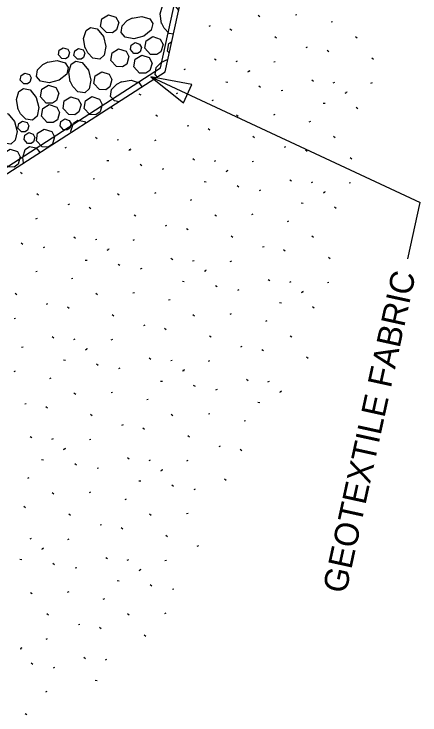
# Model space of a CAD drawing. Extents: x 2126110 to 2128246, y 1804858 to 1811658.
# Drawn here: x 2126790.5 to 2126875.2, y 1806272.7 to 1806418.7 of the extents above; entities that cross this region are included whole.
import ezdxf

# ---------------------------------------------------------------- set-up
doc = ezdxf.new("R2010")
doc.units = 0
doc.layers.add('1', color=7, linetype='Continuous')

msp = doc.modelspace()

# ---------------------------------------------------------------- linework, layer by layer
at = {"layer": '1'}
for p, q in [((2126821.03, 1806407.52), (2126844.25, 1806513.73)), ((2126822.04, 1806406.65), (2126845.41, 1806513.57)), ((2126849.19, 1806418.53), (2126849.48, 1806418.64)), ((2126841.78, 1806418.14), (2126841.43, 1806418.4)), ((2126856.62, 1806417.07), (2126856.92, 1806417.19)), ((2126831.16, 1806416.18), (2126831.46, 1806416.3)), ((2126835.89, 1806415.3), (2126835.53, 1806415.55)), ((2126845.22, 1806413.71), (2126844.87, 1806413.97)), ((2126862.04, 1806413.72), (2126861.69, 1806413.97)), ((2126851.42, 1806411.75), (2126851.72, 1806411.87)), ((2126856.15, 1806410.87), (2126855.8, 1806411.13)), ((2126822.22, 1806409.16), (2126822.61, 1806409.23)), ((2126832.67, 1806409.09), (2126832.31, 1806409.35)), ((2126836.82, 1806408.84), (2126837.12, 1806408.96)), ((2126844.67, 1806408.74), (2126844.97, 1806408.86)), ((2126865.49, 1806409.28), (2126865.13, 1806409.54)), ((2126742.89, 1806357.1), (2126821.03, 1806407.52)), ((2126825.97, 1806407.2), (2126826.27, 1806407.31)), ((2126839.41, 1806406.84), (2126839.71, 1806406.96)), ((2126743.85, 1806356.5), (2126822.04, 1806406.65)), ((2126819, 1806405.64), (2126875.16, 1806379.47)), ((2126839.28, 1806406.69), (2126839.58, 1806406.81)), ((2126834.69, 1806404.59), (2126835.09, 1806404.55)), ((2126852.93, 1806404.66), (2126852.58, 1806404.92)), ((2126857.08, 1806404.42), (2126857.38, 1806404.53)), ((2126864.93, 1806404.32), (2126865.23, 1806404.43)), ((2126841.93, 1806403.43), (2126841.58, 1806403.69)), ((2126846.23, 1806402.77), (2126846.53, 1806402.89)), ((2126859.68, 1806402.42), (2126859.97, 1806402.53)), ((2126816.98, 1806401.79), (2126816.62, 1806402.05)), ((2126824.38, 1806402.17), (2126824.68, 1806402.29)), ((2126859.54, 1806402.26), (2126859.84, 1806402.38)), ((2126831.82, 1806400.72), (2126832.12, 1806400.84)), ((2126854.95, 1806400.16), (2126855.35, 1806400.12)), ((2126811.08, 1806398.95), (2126810.73, 1806399.2)), ((2126862.2, 1806399), (2126861.84, 1806399.26)), ((2126820.42, 1806397.36), (2126820.07, 1806397.62)), ((2126837.24, 1806397.37), (2126836.89, 1806397.62)), ((2126844.65, 1806397.75), (2126844.94, 1806397.86)), ((2126826.62, 1806395.4), (2126826.92, 1806395.52)), ((2126852.08, 1806396.29), (2126852.38, 1806396.41)), ((2126831.34, 1806394.52), (2126830.99, 1806394.78)), ((2126807.86, 1806392.74), (2126807.51, 1806393)), ((2126812.02, 1806392.49), (2126812.32, 1806392.61)), ((2126819.87, 1806392.39), (2126820.17, 1806392.51)), ((2126840.68, 1806392.93), (2126840.33, 1806393.19)), ((2126857.5, 1806392.94), (2126857.15, 1806393.2)), ((2126801.17, 1806390.85), (2126801.47, 1806390.96)), ((2126846.88, 1806390.97), (2126847.18, 1806391.09)), ((2126814.47, 1806390.34), (2126814.77, 1806390.46)), ((2126814.61, 1806390.49), (2126814.91, 1806390.61)), ((2126851.61, 1806390.09), (2126851.25, 1806390.35)), ((2126809.88, 1806388.24), (2126810.28, 1806388.2)), ((2126828.13, 1806388.31), (2126827.77, 1806388.57)), ((2126832.28, 1806388.07), (2126832.58, 1806388.18)), ((2126840.13, 1806387.97), (2126840.43, 1806388.08)), ((2126860.95, 1806388.5), (2126860.59, 1806388.76)), ((2126817.13, 1806387.08), (2126816.78, 1806387.34)), ((2126821.43, 1806386.42), (2126821.73, 1806386.54)), ((2126792.17, 1806385.44), (2126791.82, 1806385.7)), ((2126799.58, 1806385.82), (2126799.88, 1806385.94)), ((2126834.74, 1806385.91), (2126835.03, 1806386.03)), ((2126834.87, 1806386.07), (2126835.17, 1806386.18)), ((2126807.02, 1806384.37), (2126807.31, 1806384.49)), ((2126830.15, 1806383.81), (2126830.55, 1806383.77)), ((2126848.39, 1806383.89), (2126848.04, 1806384.14)), ((2126852.54, 1806383.64), (2126852.84, 1806383.76)), ((2126860.39, 1806383.54), (2126860.69, 1806383.65)), ((2126837.39, 1806382.65), (2126837.04, 1806382.91)), ((2126841.69, 1806381.99), (2126841.99, 1806382.11)), ((2126795.62, 1806381.01), (2126795.27, 1806381.27)), ((2126812.44, 1806381.01), (2126812.08, 1806381.27)), ((2126819.84, 1806381.4), (2126820.14, 1806381.51)), ((2126855, 1806381.49), (2126855.3, 1806381.6)), ((2126855.14, 1806381.64), (2126855.43, 1806381.75)), ((2126801.82, 1806379.05), (2126802.12, 1806379.17)), ((2126827.28, 1806379.94), (2126827.58, 1806380.06)), ((2126850.41, 1806379.39), (2126850.81, 1806379.34)), ((2126872.59, 1806367.74), (2126875.16, 1806379.47)), ((2126806.54, 1806378.17), (2126806.19, 1806378.43)), ((2126857.66, 1806378.22), (2126857.3, 1806378.48)), ((2126815.88, 1806376.58), (2126815.53, 1806376.84)), ((2126832.7, 1806376.59), (2126832.35, 1806376.85)), ((2126840.1, 1806376.97), (2126840.4, 1806377.08)), ((2126795.06, 1806376.04), (2126795.36, 1806376.16)), ((2126822.08, 1806374.62), (2126822.38, 1806374.74)), ((2126847.54, 1806375.51), (2126847.84, 1806375.63)), ((2126826.8, 1806373.74), (2126826.45, 1806374)), ((2126803.32, 1806371.96), (2126802.97, 1806372.22)), ((2126807.48, 1806371.72), (2126807.78, 1806371.83)), ((2126836.14, 1806372.15), (2126835.79, 1806372.41)), ((2126852.96, 1806372.16), (2126852.61, 1806372.42)), ((2126792.33, 1806370.73), (2126791.97, 1806370.99)), ((2126815.33, 1806371.61), (2126815.63, 1806371.73)), ((2126796.63, 1806370.07), (2126796.93, 1806370.19)), ((2126809.93, 1806369.56), (2126810.23, 1806369.68)), ((2126810.07, 1806369.71), (2126810.37, 1806369.83)), ((2126842.34, 1806370.19), (2126842.64, 1806370.31)), ((2126847.07, 1806369.31), (2126846.71, 1806369.57)), ((2126805.34, 1806367.46), (2126805.74, 1806367.42)), ((2126823.59, 1806367.53), (2126823.23, 1806367.79)), ((2126856.41, 1806367.72), (2126856.05, 1806367.98)), ((2126812.59, 1806366.3), (2126812.24, 1806366.56)), ((2126827.74, 1806367.29), (2126828.04, 1806367.4)), ((2126835.59, 1806367.19), (2126835.89, 1806367.3)), ((2126795.04, 1806365.05), (2126795.34, 1806365.16)), ((2126816.89, 1806365.64), (2126817.19, 1806365.76)), ((2126830.2, 1806365.13), (2126830.49, 1806365.25)), ((2126830.33, 1806365.29), (2126830.63, 1806365.4)), ((2126802.48, 1806363.59), (2126802.77, 1806363.71)), ((2126843.85, 1806363.11), (2126843.5, 1806363.37)), ((2126825.61, 1806363.04), (2126826.01, 1806362.99)), ((2126832.85, 1806361.87), (2126832.5, 1806362.13)), ((2126848, 1806362.86), (2126848.3, 1806362.98)), ((2126855.85, 1806362.76), (2126856.15, 1806362.88)), ((2126791.08, 1806360.23), (2126790.73, 1806360.49)), ((2126807.9, 1806360.24), (2126807.54, 1806360.5)), ((2126815.3, 1806360.62), (2126815.6, 1806360.73)), ((2126837.15, 1806361.21), (2126837.45, 1806361.33)), ((2126850.46, 1806360.71), (2126850.76, 1806360.82)), ((2126850.6, 1806360.86), (2126850.89, 1806360.98)), ((2126822.74, 1806359.16), (2126823.04, 1806359.28)), ((2126797.28, 1806358.27), (2126797.58, 1806358.39)), ((2126802, 1806357.39), (2126801.65, 1806357.65)), ((2126845.87, 1806358.61), (2126846.27, 1806358.57)), ((2126853.11, 1806357.44), (2126852.76, 1806357.7)), ((2126811.34, 1806355.8), (2126810.99, 1806356.06)), ((2126828.16, 1806355.81), (2126827.81, 1806356.07)), ((2126835.56, 1806356.19), (2126835.86, 1806356.31)), ((2126790.52, 1806355.26), (2126790.82, 1806355.38)), ((2126843, 1806354.74), (2126843.3, 1806354.85)), ((2126817.54, 1806353.84), (2126817.84, 1806353.96)), ((2126822.26, 1806352.96), (2126821.91, 1806353.22)), ((2126798.78, 1806351.18), (2126798.43, 1806351.44)), ((2126831.6, 1806351.37), (2126831.25, 1806351.63)), ((2126848.42, 1806351.38), (2126848.07, 1806351.64)), ((2126802.94, 1806350.94), (2126803.24, 1806351.05)), ((2126810.79, 1806350.84), (2126811.09, 1806350.95)), ((2126792.09, 1806349.29), (2126792.39, 1806349.41)), ((2126805.39, 1806348.78), (2126805.69, 1806348.9)), ((2126805.53, 1806348.94), (2126805.83, 1806349.05)), ((2126837.8, 1806349.42), (2126838.1, 1806349.53)), ((2126842.53, 1806348.53), (2126842.17, 1806348.79)), ((2126819.04, 1806346.76), (2126818.69, 1806347.01)), ((2126851.87, 1806346.95), (2126851.51, 1806347.21)), ((2126800.8, 1806346.68), (2126801.2, 1806346.64)), ((2126808.05, 1806345.52), (2126807.7, 1806345.78)), ((2126823.2, 1806346.51), (2126823.5, 1806346.63)), ((2126831.05, 1806346.41), (2126831.35, 1806346.52)), ((2126790.5, 1806344.27), (2126790.8, 1806344.38)), ((2126812.35, 1806344.86), (2126812.65, 1806344.98)), ((2126825.66, 1806344.36), (2126825.95, 1806344.47)), ((2126825.79, 1806344.51), (2126826.09, 1806344.63)), ((2126797.94, 1806342.81), (2126798.23, 1806342.93)), ((2126821.07, 1806342.26), (2126821.47, 1806342.22)), ((2126828.31, 1806341.09), (2126827.96, 1806341.35)), ((2126839.31, 1806342.33), (2126838.95, 1806342.59)), ((2126843.46, 1806342.08), (2126843.76, 1806342.2)), ((2126803.36, 1806339.46), (2126803, 1806339.72)), ((2126810.76, 1806339.84), (2126811.06, 1806339.96)), ((2126832.61, 1806340.44), (2126832.91, 1806340.55)), ((2126845.92, 1806339.93), (2126846.22, 1806340.05)), ((2126846.06, 1806340.08), (2126846.35, 1806340.2)), ((2126818.2, 1806338.38), (2126818.5, 1806338.5)), ((2126792.74, 1806337.49), (2126793.04, 1806337.61)), ((2126797.46, 1806336.61), (2126797.11, 1806336.87)), ((2126841.33, 1806337.83), (2126841.73, 1806337.79)), ((2126823.62, 1806335.03), (2126823.27, 1806335.29)), ((2126831.02, 1806335.41), (2126831.32, 1806335.53)), ((2126806.8, 1806335.02), (2126806.45, 1806335.28)), ((2126838.46, 1806333.96), (2126838.76, 1806334.07)), ((2126813, 1806333.06), (2126813.3, 1806333.18)), ((2126817.72, 1806332.18), (2126817.37, 1806332.44)), ((2126794.24, 1806330.41), (2126793.89, 1806330.66)), ((2126798.4, 1806330.16), (2126798.7, 1806330.28)), ((2126806.25, 1806330.06), (2126806.54, 1806330.17)), ((2126827.06, 1806330.6), (2126826.71, 1806330.85)), ((2126800.85, 1806328.01), (2126801.15, 1806328.12)), ((2126800.99, 1806328.16), (2126801.29, 1806328.27)), ((2126833.26, 1806328.64), (2126833.56, 1806328.75)), ((2126837.99, 1806327.75), (2126837.63, 1806328.01)), ((2126796.26, 1806325.91), (2126796.66, 1806325.86)), ((2126814.5, 1806325.98), (2126814.15, 1806326.24)), ((2126818.66, 1806325.73), (2126818.96, 1806325.85)), ((2126826.51, 1806325.63), (2126826.81, 1806325.75)), ((2126803.51, 1806324.74), (2126803.16, 1806325)), ((2126807.81, 1806324.08), (2126808.11, 1806324.2)), ((2126821.12, 1806323.58), (2126821.41, 1806323.69)), ((2126821.25, 1806323.73), (2126821.55, 1806323.85)), ((2126793.39, 1806322.03), (2126793.69, 1806322.15)), ((2126816.53, 1806321.48), (2126816.93, 1806321.44)), ((2126834.77, 1806321.55), (2126834.41, 1806321.81)), ((2126823.77, 1806320.32), (2126823.42, 1806320.57)), ((2126828.07, 1806319.66), (2126828.37, 1806319.77)), ((2126798.81, 1806318.68), (2126798.46, 1806318.94)), ((2126806.22, 1806319.06), (2126806.52, 1806319.18)), ((2126813.66, 1806317.61), (2126813.96, 1806317.72)), ((2126792.92, 1806315.83), (2126792.57, 1806316.09)), ((2126802.26, 1806314.25), (2126801.91, 1806314.5)), ((2126819.08, 1806314.25), (2126818.72, 1806314.51)), ((2126826.48, 1806314.63), (2126826.78, 1806314.75)), ((2126808.46, 1806312.29), (2126808.76, 1806312.4)), ((2126813.18, 1806311.4), (2126812.83, 1806311.66)), ((2126793.86, 1806309.38), (2126794.16, 1806309.5)), ((2126801.71, 1806309.28), (2126802, 1806309.4)), ((2126822.52, 1806309.82), (2126822.17, 1806310.08)), ((2126828.72, 1806307.86), (2126829.02, 1806307.98)), ((2126796.31, 1806307.23), (2126796.61, 1806307.34)), ((2126796.45, 1806307.38), (2126796.75, 1806307.5)), ((2126791.72, 1806305.13), (2126792.12, 1806305.09)), ((2126809.96, 1806305.2), (2126809.61, 1806305.46)), ((2126814.12, 1806304.95), (2126814.42, 1806305.07)), ((2126821.97, 1806304.85), (2126822.27, 1806304.97)), ((2126798.97, 1806303.97), (2126798.62, 1806304.22)), ((2126803.27, 1806303.31), (2126803.57, 1806303.42)), ((2126816.57, 1806302.8), (2126816.87, 1806302.92)), ((2126816.71, 1806302.95), (2126817.01, 1806303.07)), ((2126811.99, 1806300.7), (2126812.39, 1806300.66)), ((2126819.23, 1806299.54), (2126818.88, 1806299.8)), ((2126823.53, 1806298.88), (2126823.83, 1806299)), ((2126794.27, 1806297.9), (2126793.92, 1806298.16)), ((2126801.68, 1806298.28), (2126801.98, 1806298.4)), ((2126809.12, 1806296.83), (2126809.42, 1806296.94)), ((2126797.72, 1806293.47), (2126797.37, 1806293.73)), ((2126814.54, 1806293.47), (2126814.18, 1806293.73)), ((2126821.94, 1806293.85), (2126822.24, 1806293.97)), ((2126803.92, 1806291.51), (2126804.22, 1806291.62)), ((2126808.64, 1806290.63), (2126808.29, 1806290.88)), ((2126797.17, 1806288.5), (2126797.46, 1806288.62)), ((2126817.98, 1806289.04), (2126817.63, 1806289.3)), ((2126791.77, 1806286.45), (2126792.07, 1806286.57)), ((2126791.91, 1806286.6), (2126792.21, 1806286.72)), ((2126805.42, 1806284.42), (2126805.07, 1806284.68)), ((2126809.58, 1806284.17), (2126809.88, 1806284.29)), ((2126794.43, 1806283.19), (2126794.08, 1806283.45)), ((2126798.73, 1806282.53), (2126799.03, 1806282.64)), ((2126807.45, 1806279.92), (2126807.84, 1806279.88)), ((2126797.14, 1806277.5), (2126797.44, 1806277.62)), ((2126793.18, 1806272.69), (2126792.83, 1806272.95))]:
    msp.add_line(p, q, dxfattribs=at)
for points in [[(2126821.27, 1806416.78), (2126820.94, 1806418.78), (2126821.46, 1806420.44), (2126822.4, 1806421.08), (2126823.77, 1806420.75), (2126824.84, 1806419.45)], [(2126809.75, 1806414.85), (2126808.56, 1806416.14), (2126808.81, 1806417.74), (2126810.19, 1806418.58), (2126811.74, 1806418.08), (2126812.34, 1806416.93), (2126811.88, 1806415.4), (2126811.02, 1806414.82), (2126809.75, 1806414.85)], [(2126815.13, 1806417.89), (2126817.13, 1806418.22), (2126818.79, 1806417.7), (2126819.43, 1806416.76), (2126819.11, 1806415.39), (2126817.54, 1806414.1), (2126815.45, 1806413.57), (2126813.67, 1806413.93), (2126812.82, 1806414.86), (2126813.03, 1806416.29), (2126814.12, 1806417.38), (2126815.22, 1806417.92)], [(2126805.35, 1806411.64), (2126805.02, 1806413.64), (2126805.54, 1806415.3), (2126806.48, 1806415.94), (2126807.84, 1806415.62), (2126809.14, 1806414.05), (2126809.67, 1806411.96), (2126809.31, 1806410.17), (2126808.38, 1806409.33), (2126806.95, 1806409.54), (2126805.86, 1806410.63), (2126805.32, 1806411.73)], [(2126823.77, 1806414.55), (2126822.87, 1806414.68), (2126821.78, 1806415.77), (2126821.24, 1806416.86)], [(2126815.49, 1806410.52), (2126814.78, 1806411.3), (2126814.93, 1806412.25), (2126815.76, 1806412.76), (2126816.69, 1806412.46), (2126817.05, 1806411.77), (2126816.78, 1806410.85), (2126816.26, 1806410.51), (2126815.49, 1806410.52)], [(2126818.99, 1806410.29), (2126817.8, 1806411.58), (2126818.06, 1806413.17), (2126819.43, 1806414.02), (2126820.98, 1806413.51), (2126821.58, 1806412.36), (2126821.13, 1806410.83), (2126820.26, 1806410.26), (2126818.99, 1806410.29)], [(2126822.9, 1806410.58), (2126822.51, 1806411.01), (2126822.76, 1806412.6), (2126823.44, 1806413.02)], [(2126800.5, 1806409.43), (2126799.79, 1806410.21), (2126799.94, 1806411.16), (2126800.76, 1806411.67), (2126801.7, 1806411.37), (2126802.05, 1806410.68), (2126801.78, 1806409.76), (2126801.26, 1806409.42), (2126800.5, 1806409.43)], [(2126803.71, 1806409.32), (2126803, 1806410.1), (2126803.15, 1806411.05), (2126803.97, 1806411.56), (2126804.91, 1806411.26), (2126805.27, 1806410.57), (2126804.99, 1806409.65), (2126804.47, 1806409.31), (2126803.71, 1806409.32)], [(2126811.88, 1806407.77), (2126810.7, 1806409.06), (2126810.95, 1806410.65), (2126812.32, 1806411.5), (2126813.88, 1806410.99), (2126814.47, 1806409.84), (2126814.02, 1806408.31), (2126813.15, 1806407.74), (2126811.88, 1806407.77)], [(2126816.69, 1806406.43), (2126815.5, 1806407.72), (2126815.76, 1806409.31), (2126817.13, 1806410.16), (2126818.68, 1806409.65), (2126819.28, 1806408.5), (2126818.83, 1806406.97), (2126817.96, 1806406.4), (2126816.69, 1806406.43)], [(2126797.51, 1806408.72), (2126799.51, 1806409.05), (2126801.18, 1806408.53), (2126801.81, 1806407.59), (2126801.49, 1806406.22), (2126799.92, 1806404.93), (2126797.83, 1806404.4), (2126796.05, 1806404.76), (2126795.2, 1806405.69), (2126795.41, 1806407.12), (2126796.5, 1806408.21), (2126797.6, 1806408.75)], [(2126802.23, 1806404.63), (2126801.9, 1806406.63), (2126802.42, 1806408.29), (2126803.36, 1806408.93), (2126804.73, 1806408.6), (2126806.02, 1806407.04), (2126806.55, 1806404.95), (2126806.2, 1806403.16), (2126805.27, 1806402.32), (2126803.83, 1806402.53), (2126802.74, 1806403.62), (2126802.2, 1806404.71)], [(2126820.39, 1806405.59), (2126819.9, 1806406.13), (2126820.12, 1806407.57), (2126821.21, 1806408.65), (2126822.3, 1806409.19)], [(2126792.52, 1806404.19), (2126791.81, 1806404.96), (2126791.96, 1806405.92), (2126792.78, 1806406.42), (2126793.72, 1806406.12), (2126794.07, 1806405.43), (2126793.8, 1806404.51), (2126793.28, 1806404.17), (2126792.52, 1806404.19)], [(2126808.34, 1806402.98), (2126807.15, 1806404.27), (2126807.41, 1806405.87), (2126808.78, 1806406.71), (2126810.33, 1806406.21), (2126810.93, 1806405.06), (2126810.48, 1806403.53), (2126809.61, 1806402.95), (2126808.34, 1806402.98)], [(2126812.39, 1806400.45), (2126811.45, 1806400.64), (2126810.6, 1806401.57), (2126810.82, 1806403.01), (2126811.91, 1806404.1), (2126813, 1806404.64)], [(2126812.91, 1806404.61), (2126814.92, 1806404.93), (2126816.58, 1806404.42), (2126817.18, 1806403.53)], [(2126791.34, 1806398.93), (2126791.01, 1806400.93), (2126791.53, 1806402.59), (2126792.47, 1806403.23), (2126793.84, 1806402.9), (2126795.13, 1806401.34), (2126795.66, 1806399.25), (2126795.31, 1806397.46), (2126794.38, 1806396.62), (2126792.94, 1806396.83), (2126791.85, 1806397.92), (2126791.31, 1806399.01)], [(2126797.22, 1806400.17), (2126796.03, 1806401.46), (2126796.28, 1806403.06), (2126797.66, 1806403.9), (2126799.21, 1806403.4), (2126799.81, 1806402.25), (2126799.36, 1806400.72), (2126798.49, 1806400.15), (2126797.22, 1806400.17)], [(2126801.91, 1806397.77), (2126800.72, 1806399.06), (2126800.97, 1806400.66), (2126802.35, 1806401.5), (2126803.9, 1806401), (2126804.5, 1806399.85), (2126804.04, 1806398.32), (2126803.18, 1806397.74), (2126801.91, 1806397.77)], [(2126806.3, 1806397.78), (2126805.12, 1806399.07), (2126805.37, 1806400.67), (2126806.74, 1806401.51), (2126808.3, 1806401.01), (2126808.89, 1806399.86), (2126808.44, 1806398.33), (2126807.57, 1806397.75), (2126806.3, 1806397.78)], [(2126797.41, 1806396.13), (2126796.22, 1806397.42), (2126796.48, 1806399.01), (2126797.85, 1806399.86), (2126799.4, 1806399.35), (2126800, 1806398.2), (2126799.55, 1806396.68), (2126798.68, 1806396.1), (2126797.41, 1806396.13)], [(2126786.8, 1806393.93), (2126786.47, 1806395.93), (2126786.99, 1806397.59), (2126787.93, 1806398.23), (2126789.3, 1806397.91), (2126790.59, 1806396.34), (2126791.12, 1806394.25), (2126790.76, 1806392.46), (2126789.83, 1806391.62), (2126788.4, 1806391.83), (2126787.31, 1806392.92), (2126786.77, 1806394.01)], [(2126800.84, 1806394.62), (2126800.13, 1806395.4), (2126800.28, 1806396.35), (2126801.1, 1806396.86), (2126802.03, 1806396.56), (2126802.39, 1806395.87), (2126802.12, 1806394.95), (2126801.6, 1806394.61), (2126800.84, 1806394.62)], [(2126802.41, 1806394.05), (2126802.36, 1806394.33), (2126802.88, 1806395.99), (2126803.82, 1806396.63), (2126805.19, 1806396.31), (2126805.44, 1806396)], [(2126792.03, 1806394.18), (2126791.31, 1806394.95), (2126791.47, 1806395.91), (2126792.29, 1806396.41), (2126793.22, 1806396.11), (2126793.58, 1806395.42), (2126793.31, 1806394.51), (2126792.79, 1806394.16), (2126792.03, 1806394.18)], [(2126793.29, 1806391.77), (2126792.58, 1806392.55), (2126792.73, 1806393.5), (2126793.56, 1806394.01), (2126794.49, 1806393.71), (2126794.85, 1806393.02), (2126794.57, 1806392.1), (2126794.05, 1806391.75), (2126793.29, 1806391.77)], [(2126796.36, 1806391.03), (2126795.17, 1806392.32), (2126795.42, 1806393.92), (2126796.8, 1806394.76), (2126798.35, 1806394.26), (2126798.95, 1806393.11), (2126798.5, 1806391.58), (2126797.63, 1806391), (2126796.36, 1806391.03)], [(2126792.49, 1806387.7), (2126792.31, 1806388.85), (2126792.82, 1806390.51), (2126793.76, 1806391.15), (2126795.13, 1806390.82), (2126795.91, 1806389.88)], [(2126789.22, 1806386.87), (2126788.04, 1806388.16), (2126788.29, 1806389.75), (2126789.67, 1806390.6), (2126791.22, 1806390.09), (2126791.81, 1806388.94), (2126791.36, 1806387.42), (2126790.5, 1806386.84), (2126789.22, 1806386.87)]]:
    msp.add_lwpolyline(points, dxfattribs=at)
msp.add_lwpolyline([(2126827.55, 1806404.07), (2126819, 1806405.64), (2126825.81, 1806400.23)], close=True, dxfattribs=at)

# ---------------------------------------------------------------- texts
msp.add_text('GEOTEXTILE FABRIC', height=5, rotation=77.6736, dxfattribs=at).set_placement((2126859.71, 1806297.8))

doc.saveas('drawing.dxf')
